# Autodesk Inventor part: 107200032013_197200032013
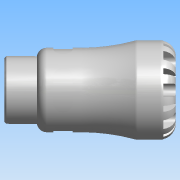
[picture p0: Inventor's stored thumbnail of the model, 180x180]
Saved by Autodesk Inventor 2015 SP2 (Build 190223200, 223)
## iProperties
Created: 2016-12
Part Number: 107200032013_197200032013
Material: PVC-Piping
Description: PLASSON MALE INTEGRAL BRASS THREAD 32X1.1/4" SERIES 1
Document SubType Name: Modeling
Designer: KIM
Mass: 61.7504 g
Surface Area: 140.097 cm^2
Volume: 44.1074 cm^3
Density: 1.4 g/cm^3
Appearance: Smooth - White
Author: KIM
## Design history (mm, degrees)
derived "1072.ipt"
feature "Solid1::1072.ipt"
tag "TaggingFeature1"
body "Solid1"
other parameters: "d1" = 23.1, "d2" = 32, "d4" = 58, "d6" = 55, "d8" = 49.3, "d13" = 7.2, "d14" = 7.2, "d15" = 0, "d17" = 360 deg, "d19" = 8 deg, "d20" = 0.64, "d21" = 0.64, "d22" = 8 deg, "d24" = 0, "d26" = 360 deg, "d32" = 5.8, "d33" = 5.8, "d34" = 39.592, "d38" = 19, "d39" = 1.18776, "d42" = 11.2, "d43" = 7.36, "d45" = 14.112, "d46" = 0, "d59" = 360 deg, "d61" = 9.52, "d62" = 0.64, "d64" = 0, "d65" = 0.58, "d68" = 4.57143, "d_" = 32, "E_" = 58, "l_" = 55, "R_" = 39.592, "l_2" = 19, "d9" = 9, "d11" = 58
